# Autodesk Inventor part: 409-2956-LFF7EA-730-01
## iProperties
Created: 2010-06
Part Number: 409-2956-LFF7EA-730-01
Material: Sch40 CS PIPE SEAMLESS
Description: PIPE
Document SubType Name: Modeling
Designer: S. Boerckel
Engineer: Steve Boerckel
Mass: 829.412 g
Surface Area: 584.074 cm^2
Volume: 105.658 cm^3
Density: 7.85 g/cm^3
Cost Center: 1-1/2"
SMR: =<COST CENTER> - <Material>
Length: 8.065 in
Title: 1-1/2"
Author: S. Boerckel
Revision Number: A
Subject: DEMIN WATER FORWARDING PUMP SKID-7EA
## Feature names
1. Extrusion1
